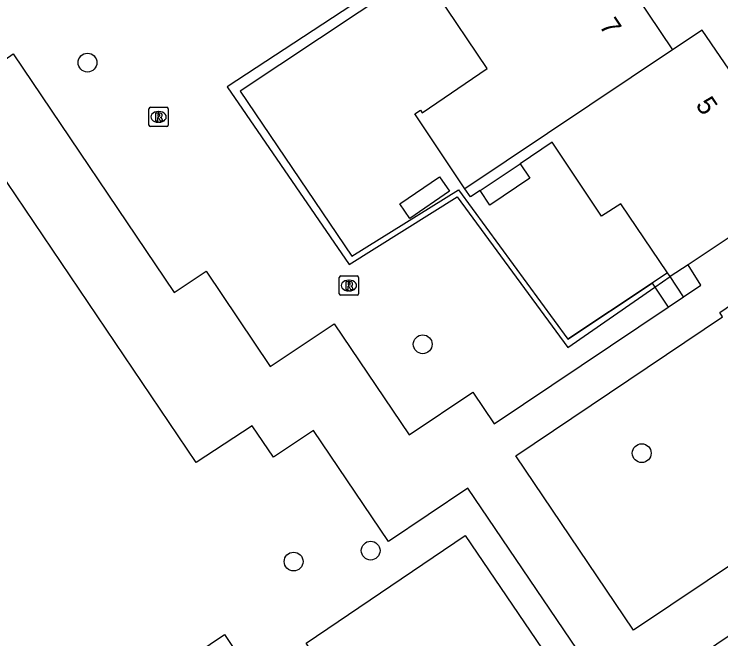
# Model space of a CAD drawing. Extents: x 158797 to 159887, y 384318 to 385255.
# Drawn here: x 159059.54 to 159096.33, y 384572.51 to 384605.03 of the extents above; entities that cross this region are included whole.
import ezdxf

# ---------------------------------------------------------------- set-up
doc = ezdxf.new("R2010")
doc.units = 0
for name, color, linetype in [('IMGEO_Boom', 7, 'Continuous'), ('IMGEO_Groenvoorziening', 7, 'Continuous'), ('IMGEO_Haag', 7, 'Continuous'), ('IMGEO_Pand', 7, 'Continuous'), ('IMGEO_Pand_nummerreeks', 7, 'Continuous'), ('IMGEO_Pand_vergunning_verleend', 7, 'Continuous'), ('IMGEO_Rioolput', 7, 'Continuous'), ('IMGEO_Voetpad_gesloten', 7, 'Continuous'), ('IMGEO_Voetpad_open', 7, 'Continuous')]:
    doc.layers.add(name, color=color, linetype=linetype)

msp = doc.modelspace()

# ---------------------------------------------------------------- linework, layer by layer
at = {"layer": 'IMGEO_Boom'}
for centre in [(159063.364, 384602.506), (159080.813, 384587.84), (159092.214, 384582.175), (159078.104, 384577.098), (159074.094, 384576.53)]:
    msp.add_circle(centre, 0.489, dxfattribs=at)
at = {"layer": 'IMGEO_Groenvoorziening'}
for points in [[(159088.369, 384588.11), (159092.755, 384591.023)], [(159088.371, 384587.681), (159092.897, 384590.811)], [(159074.744, 384572.276), (159083.027, 384577.88), (159089.501, 384568.358), (159081.187, 384562.743), (159080.913, 384563.148), (159074.744, 384572.276)]]:
    msp.add_lwpolyline(points, dxfattribs=at)
at = {"layer": 'IMGEO_Haag'}
for points in [[(159087.836, 384612.005), (159087.593, 384612.37), (159070.636, 384601.253), (159076.982, 384592.004), (159082.614, 384595.522), (159088.371, 384587.681)], [(159087.836, 384612.005), (159071.316, 384601.011), (159077.121, 384592.427), (159082.677, 384595.88), (159088.369, 384588.11)], [(159093.564, 384591.56), (159092.755, 384591.023)], [(159092.897, 384590.811), (159093.696, 384591.364)], [(159092.755, 384591.023), (159088.369, 384588.11)], [(159088.371, 384587.681), (159092.897, 384590.811)]]:
    msp.add_lwpolyline(points, dxfattribs=at)
at = {"layer": 'IMGEO_Pand'}
for points in [[(159083.012, 384595.938), (159080.41, 384599.845), (159080.693, 384600.033), (159080.783, 384599.897), (159084.167, 384602.201), (159081.553, 384606.108), (159087.113, 384609.828), (159089.059, 384606.919), (159090.613, 384607.959)], [(159090.613, 384607.959), (159093.817, 384603.172)], [(159099.27, 384595.077), (159097.319, 384598.007), (159098.877, 384599.042), (159095.354, 384604.201), (159093.817, 384603.172)], [(159093.817, 384603.172), (159083.012, 384595.938)], [(159093.564, 384591.56), (159091.13, 384595.159), (159090.126, 384594.518), (159087.557, 384598.356), (159085.886, 384597.242)], [(159085.886, 384597.242), (159086.391, 384596.49), (159084.312, 384595.093), (159083.801, 384595.854)], [(159083.801, 384595.854), (159085.886, 384597.242)], [(159082.203, 384595.805), (159080.143, 384594.395), (159079.629, 384595.146), (159081.689, 384596.556), (159082.203, 384595.805)], [(159083.801, 384595.854), (159083.293, 384595.516), (159083.012, 384595.938)], [(159097.127, 384593.65), (159094.628, 384591.985)], [(159094.628, 384591.985), (159093.696, 384591.364)], [(159093.696, 384591.364), (159093.564, 384591.56)], [(159070.501, 384572.739), (159074.142, 384567.305), (159072.525, 384566.217), (159076.912, 384559.695), (159050.979, 384542.317), (159045.281, 384550.539), (159050.945, 384554.464), (159048.565, 384557.949), (159070.501, 384572.739)]]:
    msp.add_lwpolyline(points, dxfattribs=at)
at = {"layer": 'IMGEO_Pand_vergunning_verleend'}
msp.add_lwpolyline([(159074.142, 384567.305), (159074.124, 384567.293), (159073.385, 384566.795), (159072.525, 384566.217), (159076.912, 384559.695), (159066.003, 384552.385), (159056.131, 384545.77), (159050.979, 384542.317), (159045.281, 384550.539), (159045.719, 384550.843), (159050.945, 384554.464), (159049.721, 384556.256), (159048.565, 384557.949), (159070.501, 384572.739), (159074.142, 384567.305)], dxfattribs=at)
at = {"layer": 'IMGEO_Rioolput'}
for p, q in [((159066.637, 384600.178), (159067.489, 384600.178)), ((159066.562, 384599.252), (159066.562, 384600.104)), ((159067.05, 384599.958), (159067.075, 384599.958)), ((159067.563, 384600.104), (159067.563, 384599.252)), ((159067.073, 384599.398), (159067.048, 384599.398)), ((159067.489, 384599.178), (159066.637, 384599.178)), ((159076.471, 384590.474), (159076.471, 384591.326)), ((159076.546, 384591.4), (159077.398, 384591.4)), ((159077.472, 384591.326), (159077.472, 384590.474)), ((159076.959, 384591.18), (159076.984, 384591.18)), ((159076.982, 384590.62), (159076.957, 384590.62)), ((159077.398, 384590.4), (159076.546, 384590.4))]:
    msp.add_line(p, q, dxfattribs=at)
for points in [[(159066.637, 384600.178), (159067.489, 384600.178)], [(159066.562, 384599.252), (159066.562, 384600.104)], [(159067.151, 384599.876), (159066.899, 384599.878), (159066.899, 384599.478)], [(159067.077, 384599.797), (159067.023, 384599.797), (159067.023, 384599.716)], [(159067.563, 384600.104), (159067.563, 384599.252)], [(159066.899, 384599.478), (159067.023, 384599.478), (159067.023, 384599.64), (159067.034, 384599.64)], [(159067.023, 384599.716), (159067.075, 384599.716)], [(159067.081, 384599.611), (159067.152, 384599.478), (159067.292, 384599.478), (159067.227, 384599.604)], [(159067.489, 384599.178), (159066.637, 384599.178)], [(159076.471, 384590.474), (159076.471, 384591.326)], [(159076.546, 384591.4), (159077.398, 384591.4)], [(159077.472, 384591.326), (159077.472, 384590.474)], [(159077.06, 384591.098), (159076.808, 384591.1), (159076.808, 384590.7)], [(159076.986, 384591.019), (159076.932, 384591.019), (159076.932, 384590.938)], [(159076.932, 384590.938), (159076.984, 384590.938)], [(159076.808, 384590.7), (159076.932, 384590.7), (159076.932, 384590.862), (159076.943, 384590.862)], [(159076.99, 384590.833), (159077.061, 384590.7), (159077.201, 384590.7), (159077.136, 384590.826)], [(159077.398, 384590.4), (159076.546, 384590.4)]]:
    msp.add_lwpolyline(points, dxfattribs=at)
for centre, radius, start, end in [((159066.639, 384600.102), 0.0765, 91.552, 178.448), ((159066.639, 384600.102), 0.0765, 91.552, 178.448), ((159067.487, 384600.102), 0.0765, 1.552, 88.448), ((159067.487, 384600.102), 0.0765, 1.552, 88.448), ((159067.083, 384599.701), 0.0964, 77.0061, 93.1865), ((159067.097, 384599.758), 0.0378, 276.6634, 79.6772), ((159067.15, 384599.766), 0.109, 350.3612, 89.416), ((159067.148, 384599.766), 0.112, 277.5842, 350.9817), ((159067.033, 384599.587), 0.0533, 26.0293, 88.6989), ((159067.059, 384599.905), 0.19, 274.7715, 282.9687), ((159067.132, 384599.551), 0.108, 29.5134, 73.7905), ((159066.639, 384599.254), 0.0765, 181.552, 268.448), ((159066.639, 384599.254), 0.0765, 181.552, 268.448), ((159067.487, 384599.254), 0.0765, 271.552, 358.448), ((159067.487, 384599.254), 0.0765, 271.552, 358.448), ((159076.548, 384591.324), 0.0765, 91.552, 178.448), ((159076.548, 384591.324), 0.0765, 91.552, 178.448), ((159077.396, 384591.324), 0.0765, 1.552, 88.448), ((159077.396, 384591.324), 0.0765, 1.552, 88.448), ((159076.968, 384591.127), 0.19, 274.7715, 282.9687), ((159076.992, 384590.923), 0.0964, 77.0061, 93.1865), ((159077.006, 384590.98), 0.0378, 276.6634, 79.6772), ((159077.059, 384590.988), 0.109, 350.3612, 89.416), ((159077.057, 384590.988), 0.112, 277.5842, 350.9817), ((159076.942, 384590.809), 0.0533, 26.0293, 88.6989), ((159077.041, 384590.773), 0.108, 29.5134, 73.7905), ((159076.548, 384590.476), 0.0765, 181.552, 268.448), ((159076.548, 384590.476), 0.0765, 181.552, 268.448), ((159077.396, 384590.476), 0.0765, 271.552, 358.448), ((159077.396, 384590.476), 0.0765, 271.552, 358.448)]:
    msp.add_arc(centre, radius, start, end, dxfattribs=at)
for centre, major_axis, ratio, start_param, end_param in [((159067.049, 384599.678), (-0.387, 0.002), 0.722429, 4.712389, 7.853982), ((159067.074, 384599.678), (-0.39, 0.002), 0.717154, 1.570796, 4.712389), ((159076.958, 384590.9), (-0.387, 0.002), 0.722429, 4.712389, 7.853982), ((159076.983, 384590.9), (-0.39, 0.002), 0.717154, 1.570796, 4.712389)]:
    msp.add_ellipse(centre, major_axis=major_axis, ratio=ratio, start_param=start_param, end_param=end_param, dxfattribs=at)
at = {"layer": 'IMGEO_Voetpad_gesloten'}
for points in [[(159044.054, 384613.436), (159044.228, 384613.182), (159037.615, 384608.714), (159039.816, 384605.41), (159044.001, 384608.156), (159047.314, 384603.188), (159051.455, 384605.973), (159052.578, 384604.324), (159053.4, 384604.861), (159054.5, 384603.213), (159056.994, 384604.867), (159058.651, 384602.367), (159059.496, 384602.965), (159067.874, 384590.535), (159069.539, 384591.642), (159072.876, 384586.683), (159076.198, 384588.909), (159080.104, 384583.132), (159083.425, 384585.352), (159084.526, 384583.696), (159093.592, 384589.775)], [(159107.496, 384569.245), (159106.306, 384571.022), (159102.157, 384568.249), (159100.493, 384570.74), (159099.653, 384570.193), (159097.619, 384573.232), (159091.004, 384568.778), (159083.17, 384580.346), (159079.033, 384577.582), (159075.124, 384583.348), (159073.047, 384581.967), (159071.935, 384583.601), (159069.025, 384581.685), (159057.289, 384599.045), (159053.994, 384596.838), (159051.213, 384600.975), (159035.899, 384590.661), (159037.135, 384588.782)], [(159097.56, 384576.832), (159091.785, 384572.961), (159085.665, 384582.039), (159096.425, 384589.271), (159096.281, 384589.493), (159097.934, 384590.617), (159097.358, 384591.456), (159098.192, 384592.01)], [(159094.398, 384590.316), (159095.294, 384590.917), (159094.628, 384591.985)], [(159093.592, 384589.775), (159094.398, 384590.316)]]:
    msp.add_lwpolyline(points, dxfattribs=at)
at = {"layer": 'IMGEO_Voetpad_open'}
for points in [[(159093.564, 384591.56), (159092.755, 384591.023)], [(159094.398, 384590.316), (159093.696, 384591.364)], [(159092.755, 384591.023), (159092.755, 384591.023)], [(159092.755, 384591.023), (159092.897, 384590.811)], [(159092.897, 384590.811), (159092.897, 384590.811)], [(159092.897, 384590.811), (159093.592, 384589.775)]]:
    msp.add_lwpolyline(points, dxfattribs=at)

# ---------------------------------------------------------------- texts
at = {"layer": 'IMGEO_Pand_nummerreeks'}
for s, rotation, p in [('7', 303.598, (159089.975, 384604.42)), ('5', 304.1309, (159094.99, 384600.302))]:
    msp.add_text(s, height=1, rotation=rotation, dxfattribs=at).set_placement(p)

doc.saveas('drawing.dxf')
